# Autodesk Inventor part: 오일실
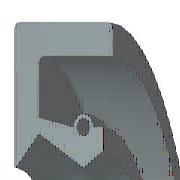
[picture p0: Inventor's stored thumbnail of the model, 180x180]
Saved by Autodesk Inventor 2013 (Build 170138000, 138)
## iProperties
IsCustomPart: 0
Created: 2009-02
Part Number: 오일실
Material: 고무
Description: 오일-실
Document SubType Name: Modeling
Standard: KS B 2804
Designer: KYOUNG IL JANG
Standards Organization: KS
Language: ko-KR
Size Designation: D - 20 32 8
Categories: <MemberInstance><Categories><Category DisplayName="샤프트 부품" InternalName="7f7aeb1f-a693-4053-b835-cee3144e0d98" Mnemonic="SHFT"><Category DisplayName="실링" Intern
Density: 0.93 g/cm^3
Mass: 2.19344 g
Surface Area: 31.4782 cm^2
Volume: 2.35853 cm^3
Author: KYOUNG IL JANG
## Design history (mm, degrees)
revolve "본체" stored, may be unused: angle "d17" = 90 deg
revolve "스프링1" stored, may be unused: angle "d18" = 90 deg
body "Solid1"
sketch "스케치1"
  geometry: L1 (0, 16)-(8, 16); L2 (8, 14.25)-(1.75, 14.25); L3 (1.75, 11.75)-(4.9, 10); L4 (4.9, 10)-(0, 10); L5 (0, 0)-(9.586, 0) reference; L6 (4.9, 10)-(6.3, 10.875); L7 (0, 18)-(0, -3) reference; L8 (-1.941, 0)-(11.507, 0) reference; L9 (4.2, 12.1)-(1.75, 12.71); L10 (1.75, 12.71)-(1.75, 14.25); L11 (0, 16)-(0, 10.088); L12 (4.9, 10)-(0, 10); L13 (1.75, 11.75)-(0.152, 10.028); L14 (8, 16)-(8, 14.25); L15 (5.6, 12.1)-(6.3, 12.1); L16 (6.3, 12.1)-(6.3, 10.875); C1 r 0.455 at (4.9, 12.1); A1 r 0.7 centre (4.9, 12.1) between (5.6, 12.1) and (4.2, 12.1); A2 r 0.088 centre (0.088, 10.088) between (0, 10.088) and (0.152, 10.028); 1 further point
  constraints: 28 end point, 5 horizontal alignment, 5 point on line, 4 point on circle, 4 vertical alignment, 3 centre point, 3 tangent, 2 collinear, 2 horizontal, 2 perpendicular, 1 coincident, 1 parallel
  dimensions: "d0" = 32 diameter of L1 L5 (= SD2); "d1" = 1.75 distance of L1.end L2.start (= SD); "d2" = 0.91 diameter of C1 (= SPDI); "d3" = 1.4 diameter of A1 (= SPDA); "d4" = 20 diameter of L3.end L5 (= NND); "d5" = 23.5 diameter of L3.start L5 (= TKDM); "d7" = 25.42 diameter of L9.end L5 (= TKDM + 0.24 x SWDT); "d8" = 1.75 distance between parallel lines of L11 L10 (= SD); "d9" = 4.9 distance from line of L11 C1.centre (= SPDST); "d10" = 24.2 diameter of C1.centre L5 (= HLDM); "d11" = 0.0875 radius of A2 (= 0.25 x LAB); "d12" = 6.3 distance between parallel lines of L11 L16 (= SDI); "d13" = 21.75 diameter of L6.end L5 (= ABDM); "d14" = 8 distance from line of L11 L1.end (= SWDT)
fillet "모깎기1" dims "d6" = 0.3 (= RR)
other parameters: "SD2" = 32 [user parameter; used in 1 equation term], "SWDT" = 8 [user parameter; used in 2 equation terms], "RR" = 0.3 [user parameter; used in 1 equation term], "SD" = 1.75 [user parameter; used in 2 equation terms], "NND" = 20 [user parameter; used in 1 equation term], "SPDA" = 1.4 [user parameter; used in 1 equation term], "SPDI" = 0.91 [user parameter; used in 1 equation term], "TKDM" = 23.5 [user parameter; used in 2 equation terms], "HLDM" = 24.2 [user parameter; used in 1 equation term], "ABDM" = 21.75 [user parameter; used in 1 equation term], "SDI" = 6.3 [user parameter; used in 1 equation term], "SPDST" = 4.9 [user parameter; used in 1 equation term], "LAB" = 0.35 [user parameter; used in 1 equation term], "d15" = 0, "d16" = 0, "d19" = 0
